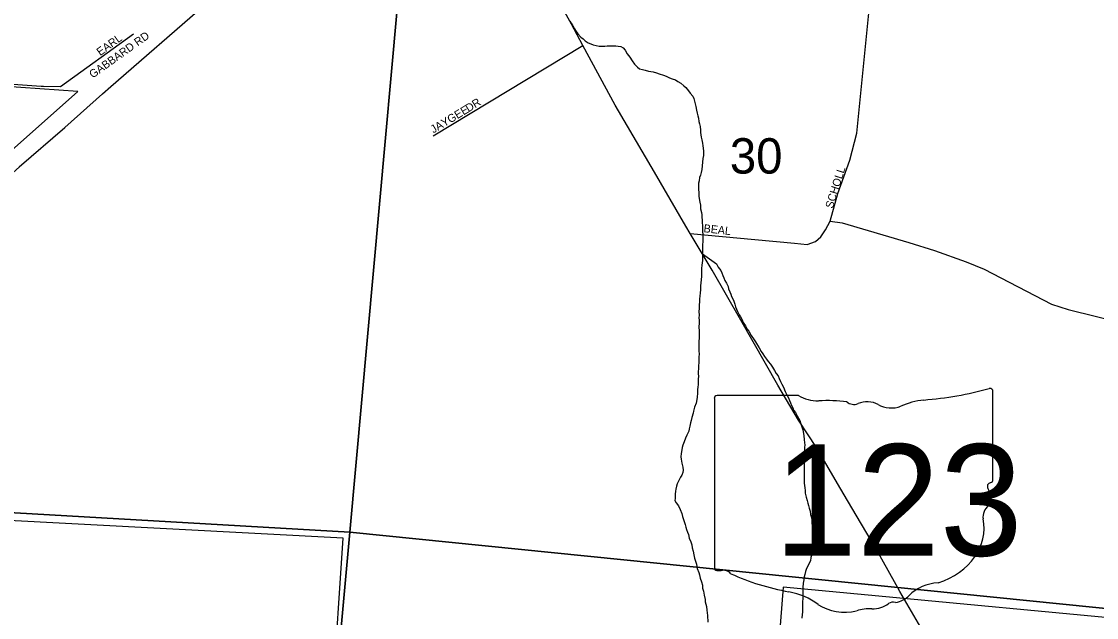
# Model space of a CAD drawing. Extents: x 0 to 1064, y 0 to 440.
# Drawn here: x 164.1 to 184.46, y 344.95 to 356.23 of the extents above; entities that cross this region are included whole.
import ezdxf

# ---------------------------------------------------------------- set-up
doc = ezdxf.new("R2010")
doc.units = 0
for name, color, linetype in [('GM_X_City_Street', 7, 'Continuous'), ('GM_X_City_Street_Text', 7, 'Continuous'), ('GM_X_Corporation', 7, 'Continuous'), ('GM_X_Interstate_Route', 7, 'Continuous'), ('GM_X_Minor_River', 7, 'Continuous'), ('GM_X_Section', 7, 'Continuous'), ('GM_X_Section_Text', 7, 'Continuous'), ('GM_X_State_Location', 7, 'Continuous'), ('GM_X_State_Route', 7, 'Continuous'), ('GM_X_State_Shield', 7, 'Continuous'), ('GM_X_Township_Road', 7, 'Continuous')]:
    doc.layers.add(name, color=color, linetype=linetype)

msp = doc.modelspace()

# ---------------------------------------------------------------- linework, layer by layer
at = {"layer": 'GM_X_City_Street'}
for points in [[(179.415, 352.448), (179.563, 352.971), (179.785, 353.601), (179.918, 354.116), (180.24, 357.338), (180.248, 357.463)], [(164.839, 355), (166.223, 355.992)], [(171.897, 354.067), (174.731, 355.775)], [(176.764, 352.216), (177.99, 352.1), (178.74, 352.032), (178.977, 352.01), (179.136, 352.067), (179.239, 352.151), (179.329, 352.284), (179.415, 352.448), (179.642, 352.416), (180.906, 352.048), (181.392, 351.894), (181.99, 351.683), (182.33, 351.543), (183.604, 350.877), (183.923, 350.781), (186.704, 350.093), (187.57, 349.918)]]:
    msp.add_lwpolyline(points, dxfattribs=at)
at = {"layer": 'GM_X_Corporation'}
for points in [[(160.253, 350.541), (165.169, 354.905), (163.363, 355.03), (164.123, 363.014), (170.541, 362.618), (169.142, 364.939), (167.565, 367.95)], [(169.996, 343.513), (170.195, 346.453), (161.943, 346.888), (161.927, 347.079), (159.236, 347.285), (159.207, 347.096), (155.643, 347.267), (155.542, 345.43), (154.208, 343.785)], [(186.837, 344.742), (178.526, 345.524), (178.23, 341.743)]]:
    msp.add_lwpolyline(points, dxfattribs=at)
at = {"layer": 'GM_X_Interstate_Route'}
for points in [[(165.793, 354.997), (167.58, 356.548), (168.201, 357.086), (168.853, 357.652), (169.619, 358.31), (170.231, 358.843), (170.929, 359.442), (171.609, 360.017), (171.987, 360.352), (172.338, 360.663), (173.525, 361.706), (174.303, 362.383), (174.507, 362.563), (175.676, 363.611), (176.331, 364.187), (176.813, 364.608), (177.233, 364.982), (177.685, 365.428), (178.236, 365.963)], [(161.445, 351.121), (161.484, 351.155), (162.308, 351.893), (163.106, 352.623), (164.064, 353.477), (164.058, 353.477), (164.923, 354.224), (165.634, 354.859), (165.793, 354.997)]]:
    msp.add_lwpolyline(points, dxfattribs=at)
at = {"layer": 'GM_X_Minor_River'}
for points in [[(174.484, 356.244), (174.513, 356.195), (174.543, 356.146), (174.572, 356.091), (174.607, 356.041), (174.636, 355.998), (174.696, 355.93), (174.737, 355.898), (174.779, 355.861), (174.833, 355.823), (174.881, 355.804), (174.929, 355.785), (174.983, 355.772), (175.044, 355.764), (175.105, 355.763), (175.147, 355.762), (175.19, 355.767), (175.244, 355.766), (175.293, 355.765), (175.354, 355.77), (175.402, 355.762), (175.45, 355.755), (175.498, 355.73), (175.534, 355.687), (175.569, 355.619), (175.622, 355.551), (175.663, 355.483), (175.71, 355.421), (175.764, 355.365), (175.805, 355.334), (175.86, 355.321), (175.914, 355.307), (175.974, 355.288)], [(175.974, 355.288), (176.017, 355.281), (176.065, 355.274), (176.125, 355.254), (176.18, 355.241), (176.258, 355.215), (176.312, 355.195), (176.372, 355.164), (176.426, 355.144), (176.487, 355.125), (176.534, 355.093), (176.588, 355.062), (176.642, 355.012), (176.684, 354.981), (176.731, 354.919), (176.766, 354.869), (176.814, 354.814), (176.831, 354.771), (176.848, 354.722), (176.87, 354.618), (176.887, 354.551), (176.898, 354.496), (176.909, 354.441), (176.92, 354.398), (176.931, 354.337), (176.942, 354.294), (176.953, 354.239), (176.957, 354.172), (176.963, 354.13), (176.968, 354.081), (176.973, 354.038), (176.984, 353.989), (176.995, 353.928), (177.006, 353.873), (177.011, 353.831), (177.016, 353.776), (177.015, 353.733), (177.014, 353.691), (177.006, 353.636), (176.999, 353.569), (176.991, 353.497), (176.984, 353.43), (176.97, 353.369), (176.963, 353.321), (176.944, 353.273), (176.937, 353.212), (176.923, 353.17), (176.922, 353.109), (176.921, 353.042), (176.926, 353), (176.93, 352.92), (176.935, 352.878), (176.946, 352.811), (176.957, 352.75), (176.961, 352.683), (176.978, 352.615), (176.983, 352.567), (176.988, 352.524), (176.993, 352.469), (176.992, 352.414), (176.997, 352.372), (176.996, 352.329), (177.001, 352.256), (177.005, 352.195), (177.004, 352.135), (177.002, 352.056), (177.001, 352.007), (177, 351.934), (176.999, 351.891), (176.997, 351.831), (176.996, 351.77), (176.995, 351.703), (176.987, 351.618), (176.979, 351.551), (176.978, 351.509), (176.977, 351.454), (176.976, 351.406), (176.975, 351.339), (176.967, 351.284), (176.96, 351.224), (176.959, 351.157), (176.951, 351.09), (176.95, 351.035), (176.942, 350.975), (176.942, 350.932), (176.934, 350.859), (176.933, 350.799), (176.931, 350.738), (176.936, 350.671), (176.929, 350.622), (176.934, 350.574), (176.933, 350.519), (176.931, 350.452), (176.935, 350.367), (176.934, 350.306), (176.933, 350.245), (176.931, 350.167), (176.93, 350.112), (176.929, 350.057), (176.927, 349.996), (176.932, 349.935)], [(176.997, 351.831), (177.266, 351.643), (177.295, 351.581), (177.343, 351.519), (177.366, 351.47), (177.383, 351.421), (177.4, 351.378), (177.423, 351.329), (177.453, 351.274), (177.482, 351.212), (177.493, 351.169), (177.516, 351.114), (177.533, 351.071), (177.55, 351.022), (177.574, 350.979), (177.591, 350.936), (177.608, 350.881), (177.625, 350.826), (177.66, 350.74), (177.695, 350.679), (177.718, 350.636), (177.747, 350.58), (177.77, 350.531), (177.811, 350.47), (177.846, 350.408), (177.876, 350.365), (177.917, 350.285), (177.964, 350.223), (177.999, 350.168), (178.04, 350.106), (178.069, 350.051), (178.11, 349.983), (178.14, 349.94), (178.175, 349.89), (178.21, 349.841), (178.24, 349.792), (178.287, 349.742), (178.322, 349.686), (178.363, 349.625), (178.393, 349.569), (178.428, 349.52), (178.451, 349.471), (178.474, 349.416), (178.497, 349.366), (178.532, 349.305), (178.561, 349.225), (178.602, 349.151), (178.625, 349.108), (178.648, 349.053), (178.666, 349.01), (178.683, 348.961), (178.706, 348.918), (178.723, 348.875), (178.759, 348.826), (178.788, 348.764), (178.817, 348.721), (178.84, 348.678), (178.863, 348.617), (178.88, 348.556), (178.897, 348.501), (178.908, 348.434), (178.919, 348.385), (178.924, 348.318), (178.928, 348.257), (178.934, 348.214), (178.932, 348.166), (178.931, 348.111), (178.93, 348.038), (178.928, 347.977), (178.927, 347.922), (178.926, 347.868), (178.925, 347.807), (178.924, 347.764), (178.923, 347.71), (178.921, 347.655), (178.926, 347.6), (178.925, 347.546), (178.924, 347.491), (178.929, 347.448), (178.934, 347.4), (178.939, 347.351), (178.944, 347.302), (178.961, 347.229), (178.977, 347.162), (178.995, 347.113), (179.006, 347.07), (179.017, 347.021), (179.034, 346.96), (179.044, 346.899), (179.061, 346.844), (179.066, 346.795), (179.071, 346.74), (179.076, 346.685), (179.075, 346.643), (179.08, 346.582), (179.079, 346.539), (179.078, 346.497)], [(176.932, 349.935), (176.931, 349.881), (176.93, 349.832), (176.929, 349.784), (176.921, 349.705), (176.92, 349.656), (176.919, 349.607), (176.918, 349.565), (176.923, 349.51), (176.916, 349.468), (176.915, 349.413), (176.913, 349.358), (176.912, 349.31), (176.905, 349.261), (176.904, 349.194), (176.896, 349.116), (176.889, 349.073), (176.875, 349.007), (176.849, 348.928), (176.83, 348.856), (176.823, 348.813), (176.797, 348.735), (176.783, 348.674), (176.77, 348.632), (176.757, 348.572), (176.743, 348.517), (176.736, 348.475), (176.704, 348.402), (176.679, 348.342), (176.653, 348.276), (176.627, 348.21), (176.614, 348.167), (176.607, 348.119), (176.594, 348.052), (176.586, 347.992), (176.591, 347.943), (176.608, 347.87), (176.624, 347.796), (176.635, 347.735), (176.628, 347.693), (176.609, 347.645), (176.584, 347.603), (176.552, 347.543), (176.52, 347.476), (176.507, 347.434), (176.494, 347.38), (176.487, 347.337), (176.48, 347.283), (176.478, 347.204), (176.477, 347.161), (176.5, 347.118), (176.542, 347.063), (176.577, 346.995), (176.605, 346.915), (176.622, 346.86), (176.645, 346.787), (176.667, 346.707), (176.685, 346.658), (176.696, 346.615), (176.713, 346.566), (176.73, 346.517), (176.747, 346.45), (176.776, 346.383), (176.793, 346.322), (176.803, 346.267), (176.82, 346.205), (176.831, 346.132), (176.848, 346.071), (176.865, 346.016), (176.882, 345.955), (176.898, 345.875), (176.927, 345.802), (176.938, 345.759), (176.955, 345.692), (176.978, 345.625), (176.995, 345.563), (176.999, 345.502), (177.016, 345.447), (177.027, 345.374), (177.049, 345.289), (177.048, 345.246), (177.071, 345.154), (177.081, 345.087), (177.086, 345.039), (177.091, 344.984), (177.101, 344.862)], [(179.078, 346.497), (179.077, 346.454), (179.076, 346.412), (179.087, 346.345), (179.092, 346.284), (179.084, 346.223), (179.07, 346.138), (179.051, 346.084), (179.044, 346.023), (179.018, 345.975), (178.999, 345.933), (178.968, 345.873), (178.948, 345.819), (178.935, 345.764), (178.922, 345.716), (178.914, 345.661), (178.907, 345.601), (178.899, 345.516), (178.898, 345.467), (178.897, 345.425), (178.896, 345.364), (178.895, 345.315), (178.893, 345.242), (178.892, 345.2), (178.891, 345.157), (178.89, 345.091), (178.889, 345.048), (178.882, 345.006), (178.88, 344.933)]]:
    msp.add_lwpolyline(points, dxfattribs=at)
at = {"layer": 'GM_X_Section'}
for points in [[(171.779, 362.681), (170.322, 346.561), (153.477, 347.535), (154.997, 363.776)], [(188.579, 361.283), (187.008, 344.881), (170.322, 346.561), (171.779, 362.681)], [(153.477, 347.535), (170.322, 346.561), (168.83, 330.174), (152.078, 331.274)], [(170.322, 346.561), (187.008, 344.881), (185.631, 328.553), (168.83, 330.174)]]:
    msp.add_lwpolyline(points, close=True, dxfattribs=at)
at = {"layer": 'GM_X_State_Route'}
for points in [[(176.684, 352.353), (176.086, 353.377), (175.347, 354.646), (174.731, 355.775), (174.519, 356.18), (174.13, 356.881), (173.894, 357.304), (173.229, 358.378), (173.019, 358.728), (172.702, 359.206)], [(179.618, 347.375), (179.154, 348.169), (178.817, 348.686), (178.427, 349.343), (177.724, 350.573), (177.183, 351.525), (176.764, 352.216), (176.684, 352.353)], [(180.665, 345.569), (180.272, 346.268), (179.741, 347.165), (179.618, 347.375)], [(181.225, 344.594), (181.131, 344.758), (180.737, 345.441), (180.665, 345.569)]]:
    msp.add_lwpolyline(points, dxfattribs=at)
at = {"layer": 'GM_X_State_Shield'}
for p, q in [((178.818, 349.15), (177.274, 349.15)), ((182.495, 347.554), (182.495, 349.229)), ((177.222, 349.095), (177.222, 345.893)), ((182.495, 347.555), (182.495, 347.554))]:
    msp.add_line(p, q, dxfattribs=at)
for centre, major_axis, start_param, end_param in [((177.282, 349.102), (0.0611, 0), 1.712693, 3.28349), ((179.186, 349.522), (0.593, 0), 4.042523, 4.731795), ((180.617, 353.515), (5.592, 0), 4.814394, 5.042369), ((182.437, 349.236), (0.0587, 0), 6.141152, 7.989035), ((179.383, 347.352), (2.127, 0), 1.404758, 1.657858), ((179.865, 349.118), (0.171, 0), 3.836095, 5.185415), ((180.116, 348.748), (0.355, 0), 0.950623, 2.079405), ((180.575, 349.256), (0.428, 0), 4.081561, 5.145723), ((181.33, 348.172), (1.125, 0), 1.699011, 2.107814), ((182.482, 347.431), (0.0909, 0), 1.883978, 3.671073), ((182.433, 347.548), (0.0628, 0), 5.05454, 6.418171), ((181.904, 347.22), (0.545, 0), 5.934695, 6.695948), ((182.706, 346.853), (0.397, 0), 2.387724, 3.262537), ((180.93, 346.64), (1.399, 0), 5.101752, 6.440018), ((177.283, 345.886), (0.0616, 0), 3.00124, 4.508301), ((177.292, 346.214), (0.47, 0), 4.665946, 4.897461), ((177.389, 345.708), (0.17, 0), 0.519207, 1.627899), ((179.53, 348.585), (4.038, 0), 4.195997, 4.488961), ((178.326, 344.455), (1.264, 0), 0.823519, 1.323587), ((181.52, 344.994), (0.766, 0), 1.647645, 2.488434), ((180.601, 345.143), (0.12, 0), 1.147584, 2.315152), ((180.549, 345.583), (0.452, 0), 4.937069, 5.64225), ((179.692, 345.692), (0.802, 0), 4.026481, 4.996735), ((180.156, 344.585), (0.659, 0), 1.495662, 1.94098), ((180.214, 345.453), (0.427, 0), 4.691044, 5.507374)]:
    msp.add_ellipse(centre, major_axis=major_axis, ratio=0.8, start_param=start_param, end_param=end_param, dxfattribs=at)
at = {"layer": 'GM_X_Township_Road'}
for points in [[(160.706, 355.273), (161.921, 355.186), (164.473, 355.007), (164.52, 355.006)], [(164.52, 355.006), (164.839, 355)]]:
    msp.add_lwpolyline(points, dxfattribs=at)

# ---------------------------------------------------------------- texts
at = {"layer": 'GM_X_City_Street_Text'}
for s, rotation, p in [('GABBARD RD', 35.6125, (165.452, 355.147)), ('EARL', 35.9152, (165.593, 355.572)), ('JAYGEE', 30.9652, (171.902, 354.107)), ('DR', 31.9931, (172.568, 354.507)), ('SCHOLL', 72.584, (179.463, 352.678)), ('BEAL', 353.6631, (177.013, 352.242))]:
    msp.add_text(s, height=0.1515, rotation=rotation, dxfattribs=at).set_placement(p)
at = {"layer": 'GM_X_Section_Text'}
msp.add_text('30', height=0.6697, rotation=0, dxfattribs=at).set_placement((177.516, 353.35))
at = {"layer": 'GM_X_State_Location'}
for s in ['s', 'r']:
    msp.add_text(s, height=0.00303, dxfattribs=at).set_placement((179.799, 347.281))
msp.add_text('123', height=0.00303, rotation=0, dxfattribs=at).set_placement((178.73, 347.061))
at = {"layer": 'GM_X_State_Shield'}
msp.add_text('123', height=2.1094, dxfattribs=at).set_placement((178.353, 346.119))

doc.saveas('drawing.dxf')
